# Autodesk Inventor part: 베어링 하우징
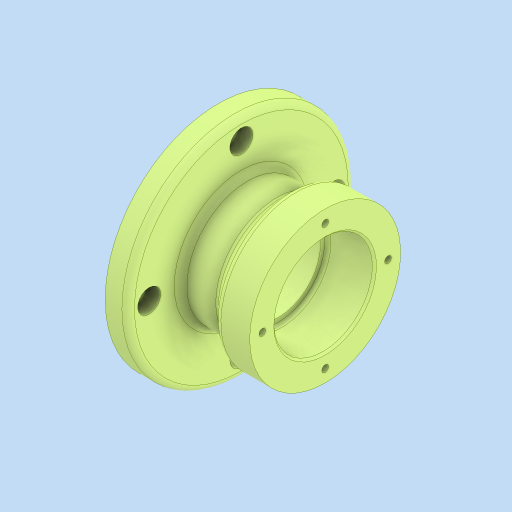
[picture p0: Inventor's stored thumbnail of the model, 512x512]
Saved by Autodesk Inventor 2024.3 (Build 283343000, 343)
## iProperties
Created: 2026-01
Part Number: 베어링 하우징
Material: 알루미늄 6061
Document SubType Name: Modeling
Designer: PC2-02
Density: 2.7 g/cm^3
Appearance: 기본값
Author: jhkim
Sending System: Autodesk Inventor 2026
Preprocessor: ST-DEVELOPER v20.1
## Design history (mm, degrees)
node "베어링 하우징1"
node "솔리드2"
node "솔리드1"
